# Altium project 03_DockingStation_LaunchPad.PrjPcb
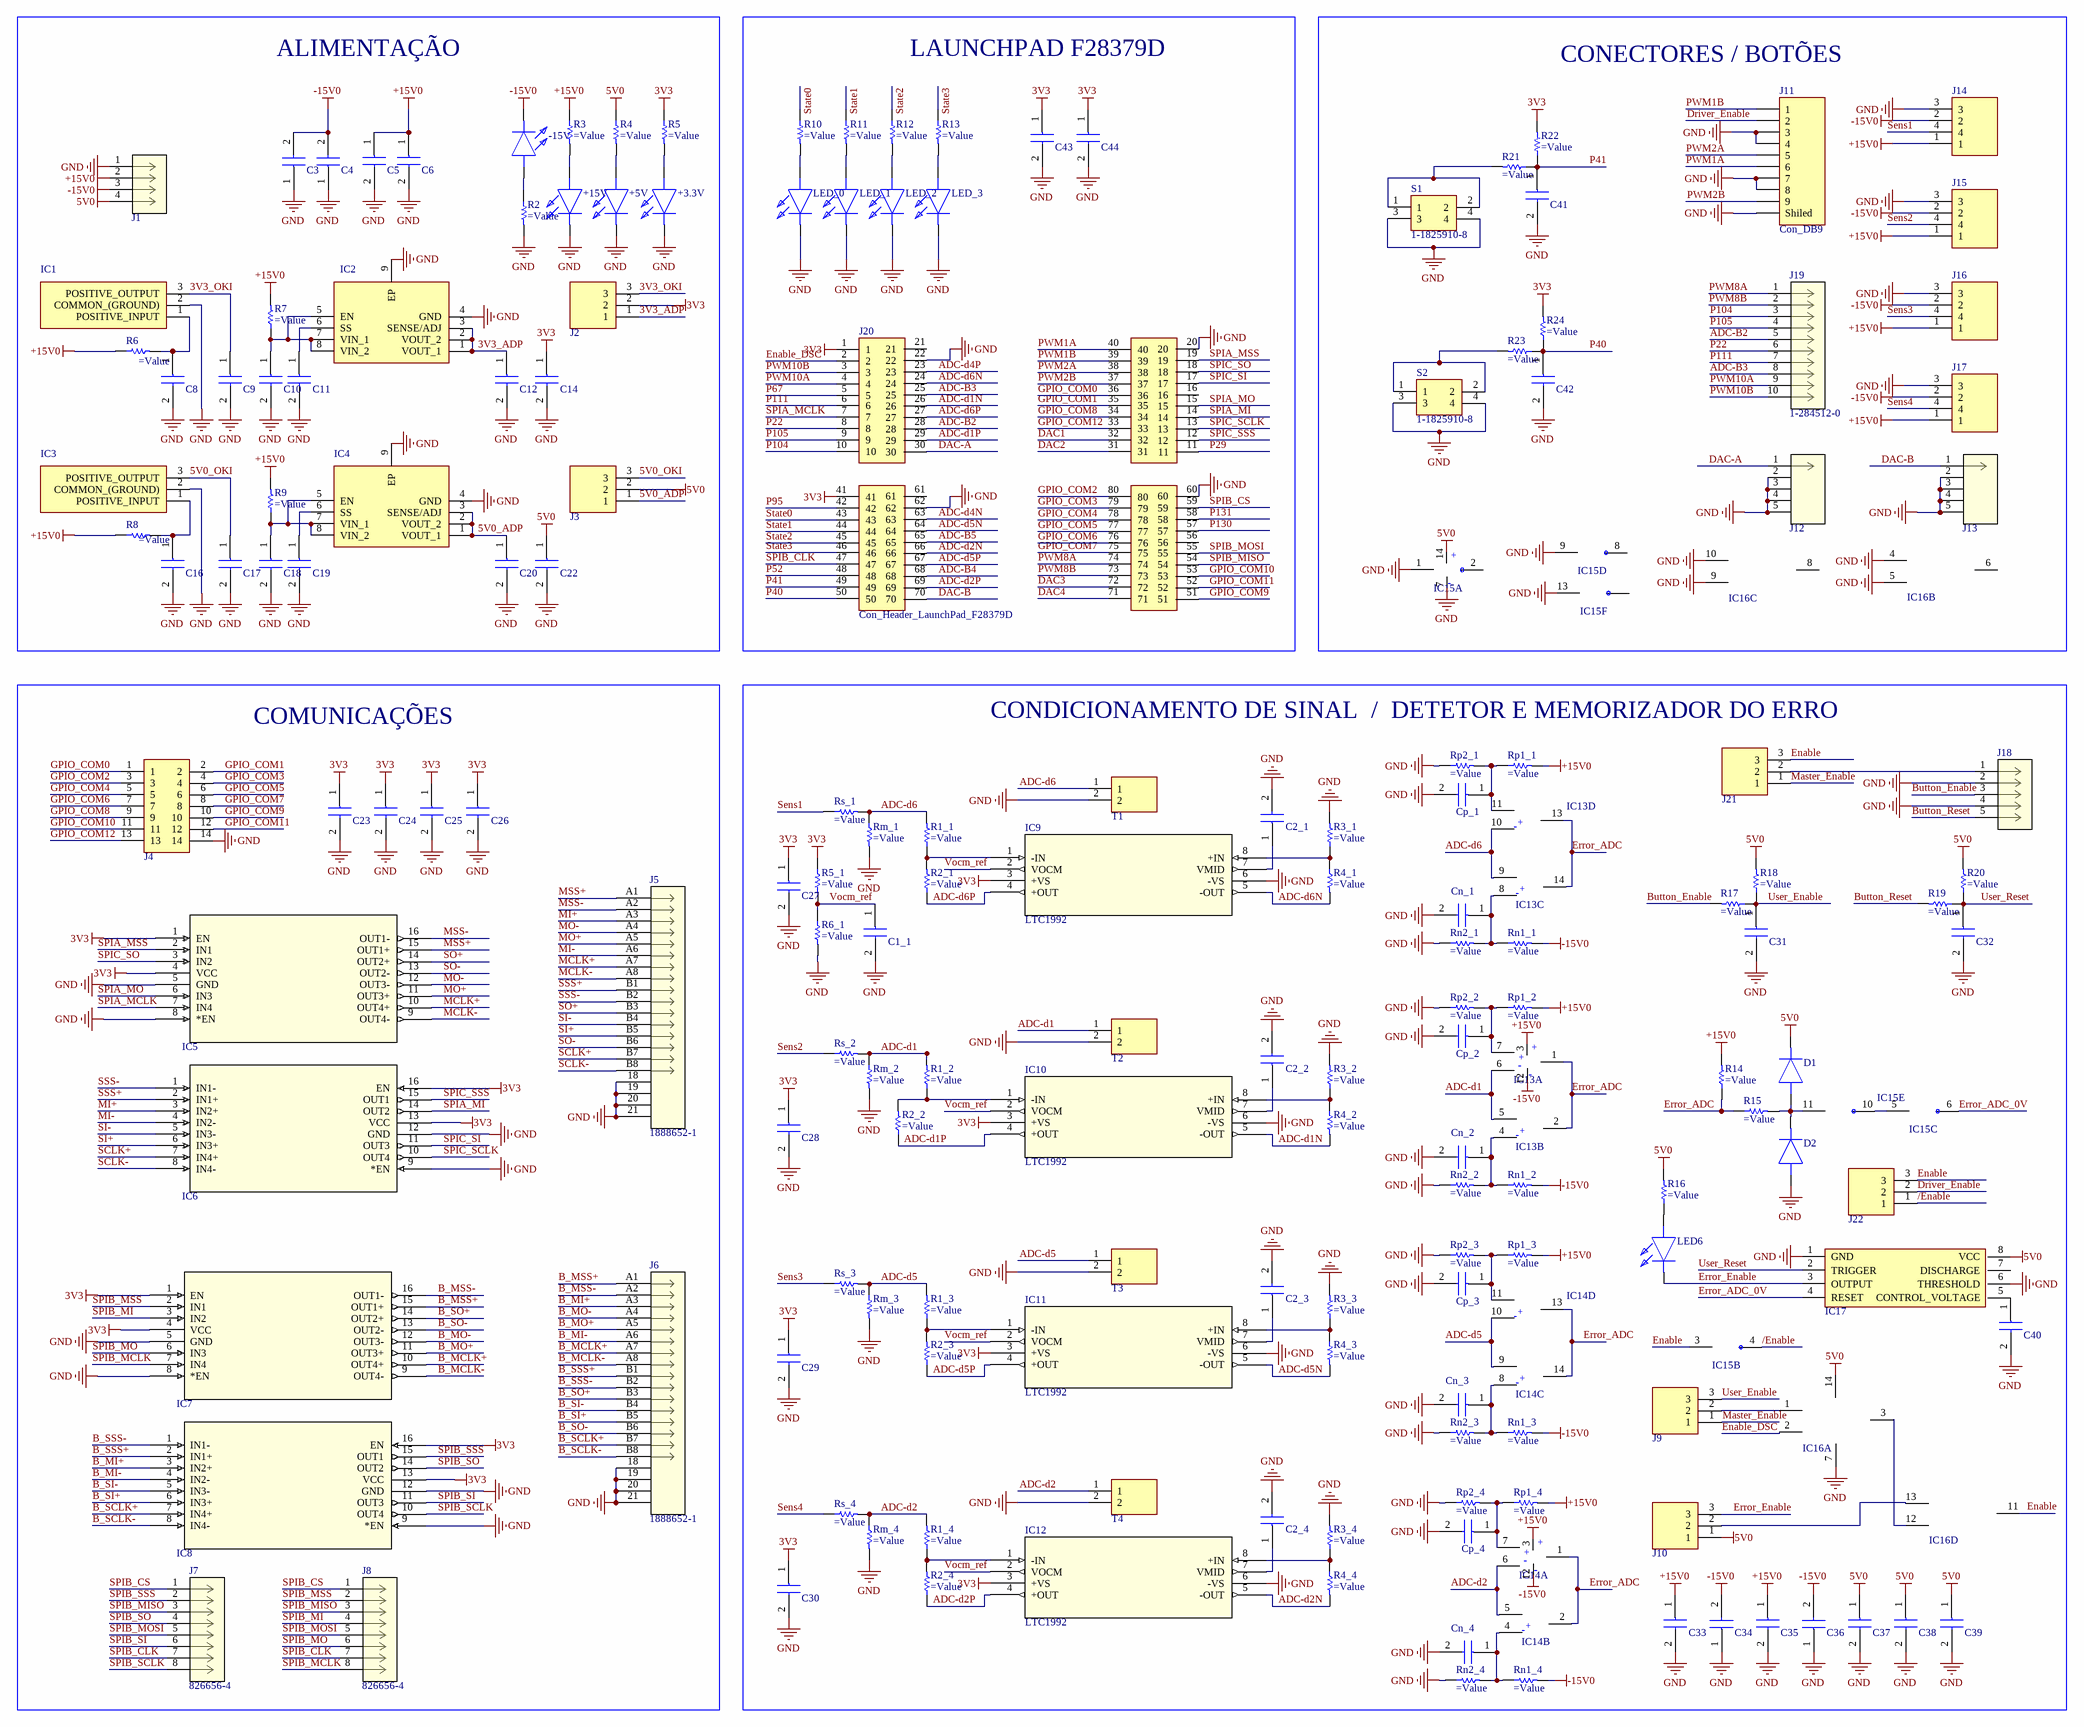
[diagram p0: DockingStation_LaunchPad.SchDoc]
1 sheet, 172 parts. Net scope: global (net labels, ports and power ports of the same name join across sheets).
Board file: DockingStation_LaunchPad.PcbDoc

## Sheet DockingStation_LaunchPad.SchDoc
size A2

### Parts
+3.3V  TLHR5400-AS12Z  [LED_SMD_1206]  (value not drawn)
+5V  TLHR5400-AS12Z  [LED_SMD_1206]  (value not drawn)
+15V  TLHR5400-AS12Z  [LED_SMD_1206]  (value not drawn)
-15V  TLHR5400-AS12Z  [LED_SMD_1206]  (value not drawn)
C1_1  CAP  [CAP1206_SMD]  (value not drawn)
C2_1  CAP  [CAP1206_SMD]  (value not drawn)
C2_2  CAP  [CAP1206_SMD]  (value not drawn)
C2_3  CAP  [CAP1206_SMD]  (value not drawn)
C2_4  CAP  [CAP1206_SMD]  (value not drawn)
C3  CAP  [CAP1206_SMD]  (value not drawn)
C4  CAP  [CAP_ELETRO_SMD_6.8]  (value not drawn)
C5  CAP  [CAP1206_SMD]  (value not drawn)
C6  CAP  [CAP_ELETRO_SMD_6.8]  (value not drawn)
C8  CAP  [CAP1206_SMD]  (value not drawn)
C9  CAP  [CAP1206_SMD]  (value not drawn)
C10  CAP  [CAP1206_SMD]  (value not drawn)
C11  CAP  [CAP1206_SMD]  (value not drawn)
C12  CAP  [CAP1206_SMD]  (value not drawn)
C14  CAP  [CAP_ELETRO_SMD_6.8]  (value not drawn)
C16  CAP  [CAP1206_SMD]  (value not drawn)
C17  CAP  [CAP1206_SMD]  (value not drawn)
C18  CAP  [CAP1206_SMD]  (value not drawn)
C19  CAP  [CAP1206_SMD]  (value not drawn)
C20  CAP  [CAP1206_SMD]  (value not drawn)
C22  CAP  [CAP_ELETRO_SMD_6.8]  (value not drawn)
C23  CAP  [CAP1206_SMD]  (value not drawn)
C24  CAP  [CAP1206_SMD]  (value not drawn)
C25  CAP  [CAP1206_SMD]  (value not drawn)
C26  CAP  [CAP1206_SMD]  (value not drawn)
C27  CAP  [CAP1206_SMD]  (value not drawn)
C28  CAP  [CAP1206_SMD]  (value not drawn)
C29  CAP  [CAP1206_SMD]  (value not drawn)
C30  CAP  [CAP1206_SMD]  (value not drawn)
C31  CAP  [CAP1206_SMD]  (value not drawn)
C32  CAP  [CAP1206_SMD]  (value not drawn)
C33  CAP  [CAP1206_SMD]  (value not drawn)
C34  CAP  [CAP1206_SMD]  (value not drawn)
C35  CAP  [CAP1206_SMD]  (value not drawn)
C36  CAP  [CAP1206_SMD]  (value not drawn)
C37  CAP  [CAP1206_SMD]  (value not drawn)
C38  CAP  [CAP1206_SMD]  (value not drawn)
C39  CAP  [CAP1206_SMD]  (value not drawn)
C40  CAP  [CAP1206_SMD]  (value not drawn)
C41  CAP  [CAP1206_SMD]  (value not drawn)
C42  CAP  [CAP1206_SMD]  (value not drawn)
C43  CAP  [CAP1206_SMD]  (value not drawn)
C44  CAP  [CAP1206_SMD]  (value not drawn)
Cn_1  CAP  [CAP1206_SMD]  (value not drawn)
Cn_2  CAP  [CAP1206_SMD]  (value not drawn)
Cn_3  CAP  [CAP1206_SMD]  (value not drawn)
Cn_4  CAP  [CAP1206_SMD]  (value not drawn)
Cp_1  CAP  [CAP1206_SMD]  (value not drawn)
Cp_2  CAP  [CAP1206_SMD]  (value not drawn)
Cp_3  CAP  [CAP1206_SMD]  (value not drawn)
Cp_4  CAP  [CAP1206_SMD]  (value not drawn)
D1  TLHR5400-AS12Z  [Diode_SMD_SOD123]  (value not drawn)
D2  TLHR5400-AS12Z  [Diode_SMD_SOD123]  (value not drawn)
IC1  OKI-78SR-3.3_1.5-W36-C  [REG_TH_3P_2.54]  (value not drawn)
IC2  ADP7118ARDZ-3.3  [IC_SMD_SOIC08_Thermal]  (value not drawn)
IC3  OKI-78SR-3.3_1.5-W36-C  [REG_TH_3P_2.54]  (value not drawn)
IC4  ADP7118ARDZ-3.3  [IC_SMD_SOIC08_Thermal]  (value not drawn)
IC5  MAX9123  [MAX91XX]  (value not drawn)
IC6  MAX91221/22  [MAX91XX]  (value not drawn)
IC7  MAX9123  [MAX91XX]  (value not drawn)
IC8  MAX91221/22  [MAX91XX]  (value not drawn)
IC9  LTC1992  [LTC1992]
IC10  LTC1992  [LTC1992]
IC11  LTC1992  [LTC1992]
IC12  LTC1992  [LTC1992]
IC13  LM339AN  [IC_SMD_SOIC14]  (value not drawn)  (parts A,B,C,D of 4)
IC14  LM339AN  [IC_SMD_SOIC14]  (value not drawn)  (parts A,B,C,D of 4)
IC15  Not Gate  [IC_SMD_SOIC14]  (value not drawn)  (parts A,B,C,D,E,F of 6)
IC16  SN7400N  [IC_SMD_SOIC14]  (value not drawn)  (parts A,B,C,D of 4)
IC17  NE555N  [IC_SMD_SOIC08]  (value not drawn)
J1  2350514-4  [CON_4Pin_Horizontal_3.5mm]  (value not drawn)
J2  22-27-2031  [HEADER_MALE_TH_3P_2.54]  (value not drawn)
J3  22-27-2031  [HEADER_MALE_TH_3P_2.54]  (value not drawn)
J4  Header 7X2  [Header_2R_14P]  (value not drawn)
J5  1888652-1  [Con_Ethernet_2x1]
J6  1888652-1  [Con_Ethernet_2x1]
J7  826656-4  [HEADER_MALE_TH_8P_2R-2.54]
J8  826656-4  [HEADER_MALE_TH_8P_2R-2.54]
J9  22-27-2031  [HEADER_MALE_TH_3P_2.54]  (value not drawn)
J10  22-27-2031  [HEADER_MALE_TH_3P_2.54]  (value not drawn)
J11  Con_DB9  [Con_DB9_Male]
J12  5-1634503-1  [CON_BNC_5-1634503-1]  (value not drawn)
J13  5-1634503-1  [CON_BNC_5-1634503-1]  (value not drawn)
J14  Con_MiniXLR_TRAPC4M  [Con_MiniXLR_TRAPC4M1X]  (value not drawn)
J15  Con_MiniXLR_TRAPC4M  [Con_MiniXLR_TRAPC4M1X]  (value not drawn)
J16  Con_MiniXLR_TRAPC4M  [Con_MiniXLR_TRAPC4M1X]  (value not drawn)
J17  Con_MiniXLR_TRAPC4M  [Con_MiniXLR_TRAPC4M1X]  (value not drawn)
J18  284512-5  [Con_5Pin_Horizontal_3.5mm]  (value not drawn)
J19  1-284512-0  [Con_10Pin_Horizontal_plugin_3.50mm]
J20  Con_Header_LaunchPad_F28379D  [LAUNCHPAD_F28379D]
J21  22-27-2031  [HEADER_MALE_TH_3P_2.54]  (value not drawn)
J22  22-27-2031  [HEADER_MALE_TH_3P_2.54]  (value not drawn)
LED6  TLHR5400-AS12Z  [LED_SMD_1206]  (value not drawn)
LED_0  TLHR5400-AS12Z  [LED_SMD_1206]  (value not drawn)
LED_1  TLHR5400-AS12Z  [LED_SMD_1206]  (value not drawn)
LED_2  TLHR5400-AS12Z  [LED_SMD_1206]  (value not drawn)
LED_3  TLHR5400-AS12Z  [LED_SMD_1206]  (value not drawn)
R1_1  Res1  [Resis_SMD_1206]  (value not drawn)
R1_2  Res1  [Resis_SMD_1206]  (value not drawn)
R1_3  Res1  [Resis_SMD_1206]  (value not drawn)
R1_4  Res1  [Resis_SMD_1206]  (value not drawn)
R2  Res1  [Resis_SMD_1206]  (value not drawn)
R2_1  Res1  [Resis_SMD_1206]  (value not drawn)
R2_2  Res1  [Resis_SMD_1206]  (value not drawn)
R2_3  Res1  [Resis_SMD_1206]  (value not drawn)
R2_4  Res1  [Resis_SMD_1206]  (value not drawn)
R3  Res1  [Resis_SMD_1206]  (value not drawn)
R3_1  Res1  [Resis_SMD_1206]  (value not drawn)
R3_2  Res1  [Resis_SMD_1206]  (value not drawn)
R3_3  Res1  [Resis_SMD_1206]  (value not drawn)
R3_4  Res1  [Resis_SMD_1206]  (value not drawn)
R4  Res1  [Resis_SMD_1206]  (value not drawn)
R4_1  Res1  [Resis_SMD_1206]  (value not drawn)
R4_2  Res1  [Resis_SMD_1206]  (value not drawn)
R4_3  Res1  [Resis_SMD_1206]  (value not drawn)
R4_4  Res1  [Resis_SMD_1206]  (value not drawn)
R5  Res1  [Resis_SMD_1206]  (value not drawn)
R5_1  Res1  [Resis_SMD_1206]  (value not drawn)
R6  Res1  [Resis_SMD_1206]  (value not drawn)
R6_1  Res1  [Resis_SMD_1206]  (value not drawn)
R7  Res1  [Resis_SMD_1206]  (value not drawn)
R8  Res1  [Resis_SMD_1206]  (value not drawn)
R9  Res1  [Resis_SMD_1206]  (value not drawn)
R10  Res1  [Resis_SMD_1206]  (value not drawn)
R11  Res1  [Resis_SMD_1206]  (value not drawn)
R12  Res1  [Resis_SMD_1206]  (value not drawn)
R13  Res1  [Resis_SMD_1206]  (value not drawn)
R14  Res1  [Resis_SMD_1206]  (value not drawn)
R15  Res1  [Resis_SMD_1206]  (value not drawn)
R16  Res1  [Resis_SMD_1206]  (value not drawn)
R17  Res1  [Resis_SMD_1206]  (value not drawn)
R18  Res1  [Resis_SMD_1206]  (value not drawn)
R19  Res1  [Resis_SMD_1206]  (value not drawn)
R20  Res1  [Resis_SMD_1206]  (value not drawn)
R21  Res1  [Resis_SMD_1206]  (value not drawn)
R22  Res1  [Resis_SMD_1206]  (value not drawn)
R23  Res1  [Resis_SMD_1206]  (value not drawn)
R24  Res1  [Resis_SMD_1206]  (value not drawn)
Rm_1  Res1  [Resis_SMD_1206]  (value not drawn)
Rm_2  Res1  [Resis_SMD_1206]  (value not drawn)
Rm_3  Res1  [Resis_SMD_1206]  (value not drawn)
Rm_4  Res1  [Resis_SMD_1206]  (value not drawn)
Rn1_1  Res1  [Resis_SMD_1206]  (value not drawn)
Rn1_2  Res1  [Resis_SMD_1206]  (value not drawn)
Rn1_3  Res1  [Resis_SMD_1206]  (value not drawn)
Rn1_4  Res1  [Resis_SMD_1206]  (value not drawn)
Rn2_1  Res1  [Resis_SMD_1206]  (value not drawn)
Rn2_2  Res1  [Resis_SMD_1206]  (value not drawn)
Rn2_3  Res1  [Resis_SMD_1206]  (value not drawn)
Rn2_4  Res1  [Resis_SMD_1206]  (value not drawn)
Rp1_1  Res1  [Resis_SMD_1206]  (value not drawn)
Rp1_2  Res1  [Resis_SMD_1206]  (value not drawn)
Rp1_3  Res1  [Resis_SMD_1206]  (value not drawn)
Rp1_4  Res1  [Resis_SMD_1206]  (value not drawn)
Rp2_1  Res1  [Resis_SMD_1206]  (value not drawn)
Rp2_2  Res1  [Resis_SMD_1206]  (value not drawn)
Rp2_3  Res1  [Resis_SMD_1206]  (value not drawn)
Rp2_4  Res1  [Resis_SMD_1206]  (value not drawn)
Rs_1  Res1  [Resis_SMD_1206]  (value not drawn)
Rs_2  Res1  [Resis_SMD_1206]  (value not drawn)
Rs_3  Res1  [Resis_SMD_1206]  (value not drawn)
Rs_4  Res1  [Resis_SMD_1206]  (value not drawn)
S1  1-1825910-8  [TACTILE-TH-4Pin]
S2  1-1825910-8  [TACTILE-TH-4Pin]
T1  TB004-508-02BE  [HEADER_MALE_TH_2P_2.54]  (value not drawn)
T2  TB004-508-02BE  [HEADER_MALE_TH_2P_2.54]  (value not drawn)
T3  TB004-508-02BE  [HEADER_MALE_TH_2P_2.54]  (value not drawn)
T4  TB004-508-02BE  [HEADER_MALE_TH_2P_2.54]  (value not drawn)

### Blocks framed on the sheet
ALIMENTAÇÃO: +3.3V +5V +15V -15V C3-C6 C8-C12 C14 C16-C20 C22 IC1-IC4 J1-J3 R2-R9
LAUNCHPAD F28379D: C43 C44 J20 LED_0-LED_3 R10-R13
CONECTORES / BOTÕES: C41 C42 IC15 IC16 J11-J17 J19 R21-R24 S1 S2
COMUNICAÇÕES: C23-C26 IC5-IC8 J4-J8

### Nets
3V3: C14.1 C23.1 C24.1 C25.1 C26.1 C27.1 C28.1 C29.1 C30.1 C43.1 C44.1 IC5.1(EN) IC5.4(VCC) IC6.13(VCC) IC6.16(EN) IC7.1(EN) IC7.4(VCC) IC8.13(VCC) IC8.16(EN) IC9.3(+VS) IC10.3(+VS) IC11.3(+VS) IC12.3(+VS) J2.2 J20.1 J20.41 R5.1 R5_1.1 R22.2 R24.2
5V0: C22.1 C37.1 C38.1 C39.1 D1.1(K) IC15.14(VCC) IC16.14(VCC) IC17.8(VCC) J1.4 J3.2 J10.1 R4.1 R16.2 R18.2 R20.2
+15V0: C5.1 C6.1 C33.1 C35.1 IC13.3(VCC) IC14.3(VCC) J1.2 J14.1 J15.1 J16.1 J17.1 R3.1 R6.1 R7.2 R8.1 R9.2 R14.2 Rp1_1.2 Rp1_2.2 Rp1_3.2 Rp1_4.2
-15V0: -15V.1(K) C3.2 C4.2 C34.2 C36.2 IC13.12(GND) IC14.12(GND) J1.3 J14.2 J15.2 J16.2 J17.2 Rn1_1.2 Rn1_2.2 Rn1_3.2 Rn1_4.2
GND: +3.3V.1(K) +5V.1(K) +15V.1(K) C1_1.2 C2_1.2 C2_2.2 C2_3.2 C2_4.2 C3.1 C4.1 C5.2 C6.2 C8.2 C9.2 C10.2 C11.2 C12.2 C14.2 C16.2 C17.2 C18.2 C19.2 C20.2 C22.2 C23.2 C24.2 C25.2 C26.2 C27.2 C28.2 C29.2 C30.2 C31.2 C32.2 C33.2 C34.1 C35.2 C36.1 C37.2 C38.2 C39.2 C40.2 C41.2 C42.2 C43.2 C44.2 Cn_1.2 Cn_2.2 Cn_3.2 Cn_4.2 Cp_1.2 Cp_2.2 Cp_3.2 Cp_4.2 D2.2(A) IC1.2(COMMON_(GROUND)) IC2.4(GND) IC2.9(EP) IC3.2(COMMON_(GROUND)) IC4.4(GND) IC4.9(EP) IC5.5(GND) IC5.8(*EN) IC6.9(*EN) IC6.12(GND) IC7.5(GND) IC7.8(*EN) IC8.9(*EN) IC8.12(GND) IC9.6(-VS) IC10.6(-VS) IC11.6(-VS) IC12.6(-VS) IC15.1(1A) IC15.7(GND) IC15.9(4A) IC15.13(6A) IC16.4(2A) IC16.5(2B) IC16.7(GND) IC16.9(3B) IC16.10(3A) IC17.1(GND) IC17.6(THRESHOLD) J1.1 J4.14 J5.18(SHIELD) J5.19(SHIELD) J5.20(SHIELD) J5.21(SHIELD) J6.18(SHIELD) J6.19(SHIELD) J6.20(SHIELD) J6.21(SHIELD) J11.3 J11.4 J11.7 J11.8 J11.10(Shiled) J12.2 J12.3 J12.4 J12.5 J13.2 J13.3 J13.4 J13.5 J14.3 J15.3 J16.3 J17.3 J18.2 J18.4 J20.20 J20.22 J20.60 J20.62 LED_0.1(K) LED_1.1(K) LED_2.1(K) LED_3.1(K) R2.2 R3_1.2 R3_2.2 R3_3.2 R3_4.2 R6_1.2 Rm_1.2 Rm_2.2 Rm_3.2 Rm_4.2 Rn2_1.1 Rn2_2.1 Rn2_3.1 Rn2_4.1 Rp2_1.1 Rp2_2.1 Rp2_3.1 Rp2_4.1 S1.3 S1.4 S2.3 S2.4 T1.2 T2.2 T3.2 T4.2
3V3_ADP: C12.1 IC2.1(VOUT_1) IC2.2(VOUT_2) IC2.3(SENSE/ADJ) J2.1
3V3_OKI: C9.1 IC1.3(POSITIVE_OUTPUT) J2.3
5V0_ADP: C20.1 IC4.1(VOUT_1) IC4.2(VOUT_2) IC4.3(SENSE/ADJ) J3.1
5V0_OKI: C17.1 IC3.3(POSITIVE_OUTPUT) J3.3
/Enable: IC15.4(2Y) J22.1
ADC-B2: J19.5 J20.28
ADC-B3: J19.8 J20.25
ADC-B4: J20.68
ADC-B5: J20.65
ADC-d1: IC13.5(2IN+) IC13.6(IN_1_(+)) R1_2.2 Rm_2.1 Rs_2.2 T2.1
ADC-d1N: IC10.5(-OUT) J20.26 R4_2.2
ADC-d1P: IC10.4(+OUT) J20.29 R2_2.1
ADC-d2: IC14.5(2IN+) IC14.6(IN_1_(+)) R1_4.2 Rm_4.1 Rs_4.2 T4.1
ADC-d2N: IC12.5(-OUT) J20.66 R4_4.2
ADC-d2P: IC12.4(+OUT) J20.69 R2_4.1
ADC-d4N: J20.63
ADC-d4P: J20.23
ADC-d5: IC14.9(3IN+) IC14.10(4IN-) R1_3.2 Rm_3.1 Rs_3.2 T3.1
ADC-d5N: IC11.5(-OUT) J20.64 R4_3.2
ADC-d5P: IC11.4(+OUT) J20.67 R2_3.1
ADC-d6: IC13.9(3IN+) IC13.10(4IN-) R1_1.2 Rm_1.1 Rs_1.2 T1.1
ADC-d6N: IC9.5(-OUT) J20.24 R4_1.2
ADC-d6P: IC9.4(+OUT) J20.27 R2_1.1
B_MCLK+: IC7.10(OUT4+) J6.A7
B_MCLK-: IC7.9(OUT4-) J6.A8
B_MI+: IC8.3(IN2+) J6.A3
B_MI-: IC8.4(IN2-) J6.A6
B_MO+: IC7.11(OUT3+) J6.A5
B_MO-: IC7.12(OUT3-) J6.A4
B_MSS+: IC7.15(OUT1+) J6.A1
B_MSS-: IC7.16(OUT1-) J6.A2
B_SCLK+: IC8.7(IN4+) J6.B7
B_SCLK-: IC8.8(IN4-) J6.B8
B_SI+: IC8.6(IN3+) J6.B5
B_SI-: IC8.5(IN3-) J6.B4
B_SO+: IC7.14(OUT2+) J6.B3
B_SO-: IC7.13(OUT2-) J6.B6
B_SSS+: IC8.2(IN1+) J6.B1
B_SSS-: IC8.1(IN1-) J6.B2
Button_Enable: J18.3 R17.2
Button_Reset: J18.5 R19.2
DAC1: J20.32
DAC2: J20.31
DAC3: J20.72
DAC4: J20.71
DAC-A: J12.1 J20.30
DAC-B: J13.1 J20.70
Driver_Enable: J11.2 J22.2
Enable: IC15.3(2A) IC16.11(4Y) J21.3 J22.3
Enable_DSC: IC16.2(1B) J20.2
Error_ADC: IC13.1(OUT_1) IC13.2(OUT2) IC13.13(OUT4) IC13.14(OUT3) IC14.1(OUT_1) IC14.2(OUT2) IC14.13(OUT4) IC14.14(OUT3) R14.1 R15.1
Error_ADC_0V: IC15.6(3Y) IC17.4(RESET)
Error_Enable: IC17.3(OUTPUT) J10.3 LED6.1(K)
GPIO_COM0: J4.1 J20.36
GPIO_COM1: J4.2 J20.35
GPIO_COM2: J4.3 J20.80
GPIO_COM3: J4.4 J20.79
GPIO_COM4: J4.5 J20.78
GPIO_COM5: J4.6 J20.77
GPIO_COM6: J4.7 J20.76
GPIO_COM7: J4.8 J20.75
GPIO_COM8: J4.9 J20.34
GPIO_COM9: J4.10 J20.51
GPIO_COM10: J4.11 J20.53
GPIO_COM11: J4.12 J20.52
GPIO_COM12: J4.13 J20.33
Master_Enable: J9.1 J21.1
MCLK+: IC5.10(OUT4+) J5.A7
MCLK-: IC5.9(OUT4-) J5.A8
MI+: IC6.3(IN2+) J5.A3
MI-: IC6.4(IN2-) J5.A6
MO+: IC5.11(OUT3+) J5.A5
MO-: IC5.12(OUT3-) J5.A4
MSS+: IC5.15(OUT1+) J5.A1
MSS-: IC5.16(OUT1-) J5.A2
P22: J19.6 J20.8
P29: J20.11
P40: C42.1 J20.50 R23.1 R24.1
P41: C41.1 J20.49 R21.1 R22.1
P52: J20.48
P67: J20.5
P95: J20.42
P104: J19.3 J20.10
P105: J19.4 J20.9
P111: J19.7 J20.6
P130: J20.57
P131: J20.58
PWM1A: J11.6 J20.40
PWM1B: J11.1 J20.39
PWM2A: J11.5 J20.38
PWM2B: J11.9 J20.37
PWM8A: J19.1 J20.74
PWM8B: J19.2 J20.73
PWM10A: J19.9 J20.4
PWM10B: J19.10 J20.3
SCLK+: IC6.7(IN4+) J5.B7
SCLK-: IC6.8(IN4-) J5.B8
Sens1: J14.4 Rs_1.1
Sens2: J15.4 Rs_2.1
Sens3: J16.4 Rs_3.1
Sens4: J17.4 Rs_4.1
SI+: IC6.6(IN3+) J5.B5
SI-: IC6.5(IN3-) J5.B4
SO+: IC5.14(OUT2+) J5.B3
SO-: IC5.13(OUT2-) J5.B6
SPIA_MCLK: IC5.7(IN4) J20.7
SPIA_MI: IC6.14(OUT2) J20.14
SPIA_MO: IC5.6(IN3) J20.15
SPIA_MSS: IC5.2(IN1) J20.19
SPIB_CLK: J7.7 J8.7 J20.47
SPIB_CS: J7.1 J8.1 J20.59
SPIB_MCLK: IC7.7(IN4) J8.8
SPIB_MI: IC7.3(IN2) J8.4
SPIB_MISO: J7.3 J8.3 J20.54
SPIB_MO: IC7.6(IN3) J8.6
SPIB_MOSI: J7.5 J8.5 J20.55
SPIB_MSS: IC7.2(IN1) J8.2
SPIB_SCLK: IC8.10(OUT4) J7.8
SPIB_SI: IC8.11(OUT3) J7.6
SPIB_SO: IC8.14(OUT2) J7.4
SPIB_SSS: IC8.15(OUT1) J7.2
SPIC_SCLK: IC6.10(OUT4) J20.13
SPIC_SI: IC6.11(OUT3) J20.17
SPIC_SO: IC5.3(IN2) J20.18
SPIC_SSS: IC6.15(OUT1) J20.12
SSS+: IC6.2(IN1+) J5.B1
SSS-: IC6.1(IN1-) J5.B2
State0: J20.43 R10.1
State1: J20.44 R11.1
State2: J20.45 R12.1
State3: J20.46 R13.1
User_Enable: C31.1 J9.3 R17.1 R18.1
User_Reset: C32.1 IC17.2(TRIGGER) R19.1 R20.1
Vocm_ref: C1_1.1 IC9.2(VOCM) IC10.2(VOCM) IC11.2(VOCM) IC12.2(VOCM) R5_1.2 R6_1.1
Net+3.3V_2: +3.3V.2(A) R5.2
Net+5V_2: +5V.2(A) R4.2
Net+15V_2: +15V.2(A) R3.2
Net-15V_2: -15V.2(A) R2.1
NetC2_1_1: C2_1.1 IC9.7(VMID)
NetC2_2_1: C2_2.1 IC10.7(VMID)
NetC2_3_1: C2_3.1 IC11.7(VMID)
NetC2_4_1: C2_4.1 IC12.7(VMID)
NetC8_1: C8.1 IC1.1(POSITIVE_INPUT) R6.2
NetC10_1: C10.1 IC2.5(EN) IC2.7(VIN_1) IC2.8(VIN_2) R7.1
NetC11_1: C11.1 IC2.6(SS)
NetC16_1: C16.1 IC3.1(POSITIVE_INPUT) R8.2
NetC18_1: C18.1 IC4.5(EN) IC4.7(VIN_1) IC4.8(VIN_2) R9.1
NetC19_1: C19.1 IC4.6(SS)
NetC40_1: C40.1 IC17.5(CONTROL_VOLTAGE)
NetCn_1_1: Cn_1.1 IC13.8(3N-) Rn1_1.1 Rn2_1.2
NetCn_2_1: Cn_2.1 IC13.4(2IN-) Rn1_2.1 Rn2_2.2
NetCn_3_1: Cn_3.1 IC14.8(3N-) Rn1_3.1 Rn2_3.2
NetCn_4_1: Cn_4.1 IC14.4(2IN-) Rn1_4.1 Rn2_4.2
NetCp_1_1: Cp_1.1 IC13.11(4IN+) Rp1_1.1 Rp2_1.2
NetCp_2_1: Cp_2.1 IC13.7(IN_1_(-)) Rp1_2.1 Rp2_2.2
NetCp_3_1: Cp_3.1 IC14.11(4IN+) Rp1_3.1 Rp2_3.2
NetCp_4_1: Cp_4.1 IC14.7(IN_1_(-)) Rp1_4.1 Rp2_4.2
NetD1_2: D1.2(A) D2.1(K) IC15.11(5A) R15.2
NetIC9_1: IC9.1(-IN) R1_1.1 R2_1.2
NetIC9_8: IC9.8(+IN) R3_1.1 R4_1.1
NetIC10_1: IC10.1(-IN) R1_2.1 R2_2.2
NetIC10_8: IC10.8(+IN) R3_2.1 R4_2.1
NetIC11_1: IC11.1(-IN) R1_3.1 R2_3.2
NetIC11_8: IC11.8(+IN) R3_3.1 R4_3.1
NetIC12_1: IC12.1(-IN) R1_4.1 R2_4.2
NetIC12_8: IC12.8(+IN) R3_4.1 R4_4.1
NetIC15_5: IC15.5(3A) IC15.10(5Y)
NetIC16_1: IC16.1(1A) J9.2
NetIC16_3: IC16.3(1Y) IC16.12(4B)
NetIC16_13: IC16.13(4A) J10.2
NetJ18_1: J18.1 J21.2
NetLED6_2: LED6.2(A) R16.1
NetLED_0_2: LED_0.2(A) R10.2
NetLED_1_2: LED_1.2(A) R11.2
NetLED_2_2: LED_2.2(A) R12.2
NetLED_3_2: LED_3.2(A) R13.2
NetR21_2: R21.2 S1.1 S1.2
NetR23_2: R23.2 S2.1 S2.2

Not connected (* = marked no-connect by the designer): IC15 2(1Y) 8(4Y) 12(6Y); IC16 6(2Y) 8(3Y); IC17 7(DISCHARGE); J20 16 21 56 61

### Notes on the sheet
- CONDICIONAMENTO DE SINAL  /  DETETOR E MEMORIZADOR DO ERRO

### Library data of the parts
+3.3V +5V +15V -15V LED6 LED_0-LED_3 = LED: Manufacturer_Name: Vishay
C1_1 C2_1-C2_4 C3-C6 C8-C12 C14 C16-C20 C22-C44 Cn_1-Cn_4 Cp_1-Cp_4 = CAP: Capacitor; Manufacturer_Name: Kemet; Manufacturer_Part_Number: C1206X475K3RACAUTO7210
D1 D2 = Diode: Manufacturer_Name: Vishay
IC1 IC3 = Regulador_3.3_1.5: Power Supply; Manufacturer_Name: Murata Electronics; Manufacturer_Part_Number: OKI-78SR-3.3/1.5-W36-C
IC2 IC4 = ADP7118ARDZ-5.0: Power Supply; Manufacturer_Name: Analog Devices
IC5 IC7 = MAX9123: No Description Available; Mfr_Name: Maxim Integrated Products; Manufacturer_Part_Number: MAX9123EUE+
IC6 IC8 = MAX9121/22: No Description Available; Mfr_Name: Maxim Integrated Products; Manufacturer_Part_Number: MAX9122EUE+
IC9-IC12 = LTC1992: No Description Available; Mfr_Name: Analog Devices / Linear Technology; Manufacturer_Part_Number: LTC1992IMS8#PBF
IC13 IC14 = LM339: Integrated Circuit; Manufacturer_Name: Texas Instruments
IC15 = 7404_Not: Integrated Circuit; Manufacturer_Name: Texas Instruments; Manufacturer_Part_Number: LM339AN
IC16 = SN7408: Integrated Circuit; Manufacturer_Name: Texas Instruments
IC17 = NE555: Integrated Circuit; Manufacturer_Name: ST
J1 = Con_4Pin_Horizontal_Plugin_3.5mm: No Description Available; Mfr_Name: TE Connectivity
J2 J3 J9 J10 J21 J22 = Con_Header_3P: Connector; Manufacturer_Name: Molex
J4 = Con_Header_14P: Connector dual row
J5 J6 = Con_Ethernet_2x1: No Description Available; Mfr_Name: TE Connectivity
J7 J8 = Con_Header_8P_2R: No Description Available; Mfr_Name: TE Connectivity
J11 = Con_DB9: DB9 (Right angle  PCB mount); ASiD Part Number: DB9-AS
J12 J13 = Con_BNC_Vertical_5-1634503-1: No Description Available; Mfr_Name: TE Connectivity
J14-J17 = Con_MiniXLR_TRAPC4M: Connector; Manufacturer_Name: Switchcraft; Manufacturer_Part_Number: TRAPC4M1X
J18 = Con_5Pin_Horizontal_plugin_3.5mm: Conector 5 Pinos 3.5mm; Mfr_Name: TE Connectivity
J19 = Con_10Pin_Horizontal_plugin_3.50mm: No Description Available; Mfr_Name: TE Connectivity
J20 = Con_Header_LaunchPad_F28379D: LaunchPad F28379D
R1_1-R1_4 R2 R2_1-R2_4 R3 R3_1-R3_4 R4 R4_1-R4_4 R5 R5_1 R6 R6_1 R7-R24 Rm_1-Rm_4 Rn1_1-Rn1_4 Rn2_1-Rn2_4 Rp1_1-Rp1_4 Rp2_1-Rp2_4 Rs_1-Rs_4 = Resistor
S1 S2 = Button: Switch; Manufacturer_Name: TE Connectivity
T1-T4 = Con_Header_2P: Connector; Manufacturer_Name: CUI Devices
